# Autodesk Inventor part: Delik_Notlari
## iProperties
Created: 2005-02
Part Number: Delik_Notlari
Document SubType Name: Modeling
Designer: Dale Schneider
Density: 1 g/cm^3
Author: Dale Schneider
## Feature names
1. Extrusion1
2. Extrusion2
3. Extrusion3
4. Extrusion4
5. Extrusion5
6. Fillet1
7. Circular Pattern1
8. Extrusion6
9. Fillet2
10. Mirror1
11. Extrusion7
12. Hole1
13. Hole2
14. Mirror3
15. Hole3
16. Hole4
17. Hole5
18. Hole6
19. Mirror2
